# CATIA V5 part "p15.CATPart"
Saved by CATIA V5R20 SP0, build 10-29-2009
Part number: p15
Bounding box of the stored display mesh (mm): x -10 to 0, y -24.997 to 70.347, z 35.002 to 91.406
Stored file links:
  D:\Dropbox\IAO_2011\MMS_GR2\IAO_2011_1439_jlicbarski\p15.CATPart
  D:\Dropbox\IAO_2011\MMS_GR2\IAO_2011_1439_jlicbarski\train.CATProduct
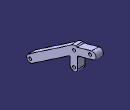
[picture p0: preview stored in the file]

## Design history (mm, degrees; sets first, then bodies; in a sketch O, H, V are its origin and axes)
Parameters
  LENGTH = 9.789 mm
  LENGTH = 0 mm
AxisSystem1: origin (0, 0, 0), X (1, 0, 0), Y (0, 1, 0), Z (0, 0, 1)
Set1
  Plane1: linked copy from another document
  Line1 to Line5: linked copy from another document
Body1 (main body)
  Sketch1 on Plane1, origin (0, 0, 0), H (0, 1, 0), V (0, 0, 1)
    point P1 (45, 60)
    line L1 (45, 60) -> (45, 73.9432)
    point P2 (35.027, 59.4814)
    line L2 (35.027, 59.4814) -> (35.027, 69.54)
    line L3 (33.4887, 70.3538) -> (-17.1869, 35.8664)
    point P3 (-17.1869, 35.8664)
    point P4 (-22.8131, 44.1336)
    line L4 (-22.8131, 44.1336) -> (35.027, 83.4968)
    line L5 (35.027, 83.4968) -> (35.8099, 84.212)
    arc A1 centre (41.262, 78.2438) radius 8.0837 from (35.8099, 84.212) to (42.1275, 86.281) cw
    reference projected point E1 (-20, 40) from Line2
    arc A2 centre (34.0425, 69.54) radius 0.9844 from (33.4887, 70.3538) to (35.027, 69.54) cw
    arc A3 centre (40, 60) radius 5 from (35.027, 59.4814) to (45, 60) ccw
    point P13 (35.027, 59.4814)
    point P14 (45, 60)
    arc A4 centre (-20, 40) radius 5 from (-22.8131, 44.1336) to (-17.1869, 35.8664) ccw
    point P15 (-22.8131, 44.1336)
    point P16 (-17.1869, 35.8664)
    line L6 (45, 73.9432) -> (45, 75.8667)
    line L7 (45, 75.8667) -> (66.7442, 81.7901)
    point P19 (64.1713, 91.2349)
    line L8 (64.1713, 91.2349) -> (44.17, 85.7863)
    line L9 (44.17, 85.7863) -> (42.1275, 86.281)
    arc A5 centre (65.4577, 86.5125) radius 4.8945 from (66.7442, 81.7901) to (64.1713, 91.2349) ccw
    point P21 (65.4577, 86.5125)
    distance L3 L4 = 10
    distance L3 E1 = 5
    distance L8 L7 = 9.789 {= LENGTH}
    radius A5 = 4.8945 {= LENGTH /2}
    distance P21 P19 = 4.8945 {= LENGTH /2}
    coincidence: P1 P14, P2 P13, P3 P16, P4 P15
  Pad1: profile Sketch1, direction (-1, 0, 0), length 10
  Sketch2 on start face of Pad1, origin (0, 0, 0), H (0, 1, 0), V (0, 0, 1)
    circle A1 centre (62, 86) radius 2
    reference projected point E1 (62, 86) from Line3
    radius A1 = 2
    distance A1 E1 = 2
  Pocket1: profile Sketch2, direction (-1, 0, 0), length 58
  Sketch3 on end face of Pad1, origin (-10, 0, 0), H (0, -1, 0), V (0, 0, 1)
    circle A1 centre (-40, 60) radius 2
    reference projected point E1 (-40, 60) from Line1
    radius A1 = 2
    distance A1 E1 = 2
  Pocket2: profile Sketch3, direction (1, 0, 0), length 58
  Sketch4 on start face of Pad1, origin (0, 0, 0), H (0, 1, 0), V (0, 0, 1)
    circle A1 centre (-20, 40) radius 2
    reference projected point E1 (-20, 40) from Line2
    radius A1 = 2
    distance A1 E1 = 2
  Pocket3: profile Sketch4, direction (-1, 0, 0), length 58
  Sketch5 on start face of Pad1, origin (0, 0, 0), H (0, 1, 0), V (0, 0, 1)
    circle A1 centre (40, 80) radius 2
    reference projected point E1 (40, 80) from Line5
    radius A1 = 2
    distance A1 E1 = 2
  Pocket4: profile Sketch5, direction (-1, 0, 0), length 58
